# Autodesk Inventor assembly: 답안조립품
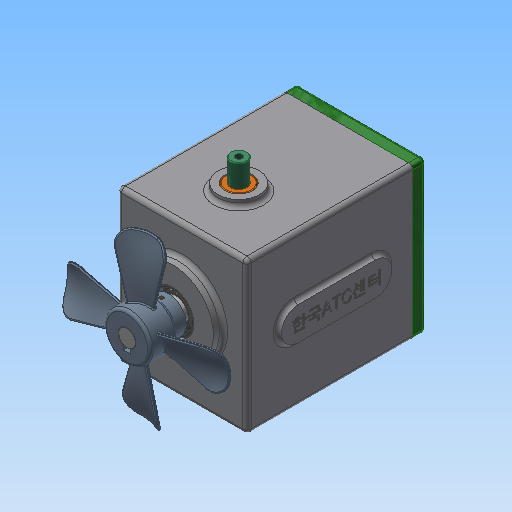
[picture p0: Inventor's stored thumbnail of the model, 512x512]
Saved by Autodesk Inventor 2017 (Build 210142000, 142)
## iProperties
Part Number: 답안조립품
Material: 일반
Document SubType Name: Assembly
Designer: MRC
Mass: 2669.46 g
Surface Area: 1952.92 cm^2
Volume: 798.897 cm^3
Density: 3.34143 g/cm^3
Author: MRC
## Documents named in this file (17)
- C:\Users\MRC\Desktop\610205V1007\답안조립품.iam
- C:\Users\MRC\Desktop\610205V1007\본체.ipt
- C:\Users\MRC\Desktop\610205V1007\가변스프링.ipt
- C:\Users\MRC\Desktop\610205V1007\멈춤나사 M3x8.ipt
- C:\Users\MRC\Desktop\610205V1007\메인 기어 축.ipt
- C:\Users\MRC\Desktop\610205V1007\베어링 608.ipt
- C:\Users\MRC\Desktop\610205V1007\베어링 6903.ipt
- C:\Users\MRC\Desktop\610205V1007\볼트 M4 x 10.ipt
- C:\Users\MRC\Desktop\610205V1007\부시.ipt
- C:\Users\MRC\Desktop\610205V1007\서브 기어 축.ipt
- C:\Users\MRC\Desktop\610205V1007\슬라이더.ipt
- C:\Users\MRC\Desktop\610205V1007\오일 실 8 22 7.ipt
- C:\Users\MRC\Desktop\610205V1007\오일 실 17 30 8.ipt
- C:\Users\MRC\Desktop\610205V1007\커버.ipt
- C:\Users\MRC\Desktop\610205V1007\키 5 x 5 x 24.ipt
- C:\Users\MRC\Desktop\610205V1007\팬날개.ipt
- 팬날개.ipt
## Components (1 placed, 1 different names)
1. 가변스프링:1
